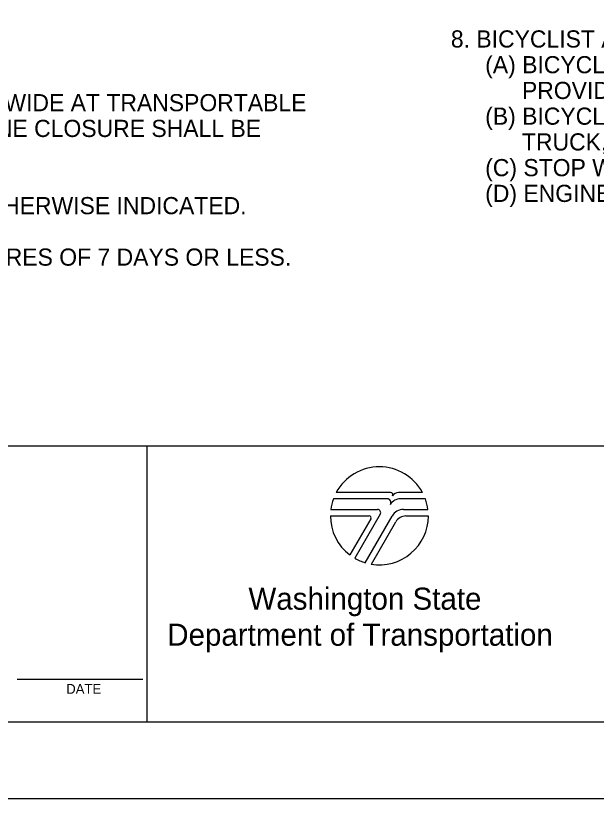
# Model space of a CAD drawing. Extents: x 99999.1 to 100055.7, y 99995 to 100013.2.
# Drawn here: x 100009.773 to 100012.143, y 99999.687 to 100002.881 of the extents above; entities that cross this region are included whole.
import ezdxf

# ---------------------------------------------------------------- set-up
doc = ezdxf.new("R2010")
doc.units = 0
for name, color, linetype in [('SH_GI_GeneralNotesBodyText', 7, 'Continuous'), ('SH_GI_PlotLimits', 7, 'Continuous'), ('SH_GI_SheetBorder', 7, 'Continuous'), ('SH_GI_SheetTextInCells', 7, 'Continuous'), ('SH_GI_WSDOTLogo', 7, 'Continuous')]:
    doc.layers.add(name, color=color, linetype=linetype)

msp = doc.modelspace()

# ---------------------------------------------------------------- linework, layer by layer
at = {"layer": 'SH_GI_PlotLimits'}
msp.add_lwpolyline([(99999.0625, 99999.6875), (100016.0625, 99999.6875), (100016.0625, 100010.6875), (99999.0625, 100010.6875)], close=True, dxfattribs=at)
at = {"layer": 'SH_GI_SheetBorder'}
for p, q in [((100000, 100001.1259), (100015.75, 100001.1259)), ((100010.3089, 100001.1259), (100010.3089, 100000)), ((100009.7797, 100000.1733), (100010.2914, 100000.1733)), ((100000, 100000), (100015.75, 100000))]:
    msp.add_line(p, q, dxfattribs=at)
at = {"layer": 'SH_GI_WSDOTLogo'}
for p, q in [((100011.303, 100000.9354), (100011.0815, 100000.9354)), ((100011.433, 100000.9354), (100011.3351, 100000.9354)), ((100011.2894, 100000.9094), (100011.0697, 100000.9094)), ((100011.343, 100000.9094), (100011.3429, 100000.9094)), ((100011.4448, 100000.9094), (100011.343, 100000.9094)), ((100011.0572, 100000.84), (100011.2148, 100000.84)), ((100011.059, 100000.8661), (100011.2496, 100000.8661)), ((100011.261, 100000.8464), (100011.1567, 100000.6672)), ((100011.3558, 100000.8661), (100011.4555, 100000.8661)), ((100011.3655, 100000.8394), (100011.4572, 100000.8394)), ((100011.222, 100000.8277), (100011.1364, 100000.6807)), ((100011.1989, 100000.6487), (100011.3089, 100000.839)), ((100011.2244, 100000.6428), (100011.3242, 100000.8156))]:
    msp.add_line(p, q, dxfattribs=at)
for centre, radius, start, end in [((100011.2572, 100000.84), 0.2, 28.4787, 151.532), ((100011.303, 100000.9263), 0.00903, 329.8742, 90.0033), ((100011.3352, 100000.9066), 0.0287, 90.0072, 148.1676), ((100011.2572, 100000.84), 0.2, 159.696, 172.5057), ((100011.2894, 100000.8946), 0.0148, 327.8418, 89.9985), ((100011.3429, 100000.861), 0.0484, 89.9953, 147.8238), ((100011.2572, 100000.84), 0.2, 7.4943, 20.2941), ((100011.2572, 100000.84), 0.2, 179.9986, 232.8433), ((100011.2149, 100000.8318), 0.0082, 329.7436, 90), ((100011.2572, 100000.84), 0.2, 260.5455, 359.8086), ((100011.2497, 100000.853), 0.0131, 329.7683, 90), ((100011.3558, 100000.8119), 0.0542, 90, 149.9974), ((100011.3654, 100000.7918), 0.0476, 90, 150.0543), ((100011.2572, 100000.84), 0.2, 239.7929, 253.0448)]:
    msp.add_arc(centre, radius, start, end, dxfattribs=at)

# ---------------------------------------------------------------- texts
at = {"layer": 'SH_GI_GeneralNotesBodyText'}
for s, p in [('8. BICYCLIST ACCOMMODATIONS, WHERE FACILITY OPEN TO BICYCLES:', (100011.549, 100002.7506)), ('(A) BICYCLES PROHIBITED VIA R5-601 (IF EXIT-RAMP PRESENT) & R5-6 SIGNS. ', (100011.689, 100002.6456)), ('PROVIDE SIGNED DETOUR OR ALTERNATIVE ROUTE.', (100011.839, 100002.5406)), ('4. IF PAVED SHOULDER IS LESS THAN 8 FEET WIDE AT TRANSPORTABLE ', (100007.6204, 100002.4906)), ('(B) BICYCLES PROHIBITED VIA R5-6 SIGN(S). PROVIDE FREE SHUTTLE (WORK ', (100011.689, 100002.4356)), ('ATTENUATOR AND WORK AREA, THEN A LANE CLOSURE SHALL BE ', (100007.7004, 100002.3856)), ('TRUCK, VAN, OR BUS OK) + CONTACT INFORMATION/PHONE BOX/LABORER. ', (100011.839, 100002.3306)), ('(C) STOP WORK OPS. & ESCORT BICYCLISTS THROUGH SHOULDER CLOSURE.', (100011.689, 100002.2256)), ('(D) ENGINEER TO ACCEPT ANY ALTERNATIVE STRATEGIES.', (100011.689, 100002.1206)), ('5. SIGNS ARE BLACK ON ORANGE UNLESS OTHERWISE INDICATED.', (100007.6204, 100002.0706)), ('6. PLAN IS APPLICABLE TO SHOULDER CLOSURES OF 7 DAYS OR LESS.', (100007.6204, 100001.8606))]:
    msp.add_text(s, height=0.07, rotation=360, dxfattribs=at).set_placement(p)
at = {"layer": 'SH_GI_SheetTextInCells'}
for s, height, p in [('Washington State', 0.090072, (100010.7229, 100000.4571)), ('Department of Transportation', 0.090072, (100010.3916, 100000.3101)), ('DATE', 0.04003, (100009.9794, 100000.1141))]:
    msp.add_text(s, height=height, dxfattribs=at).set_placement(p)

doc.saveas('drawing.dxf')
